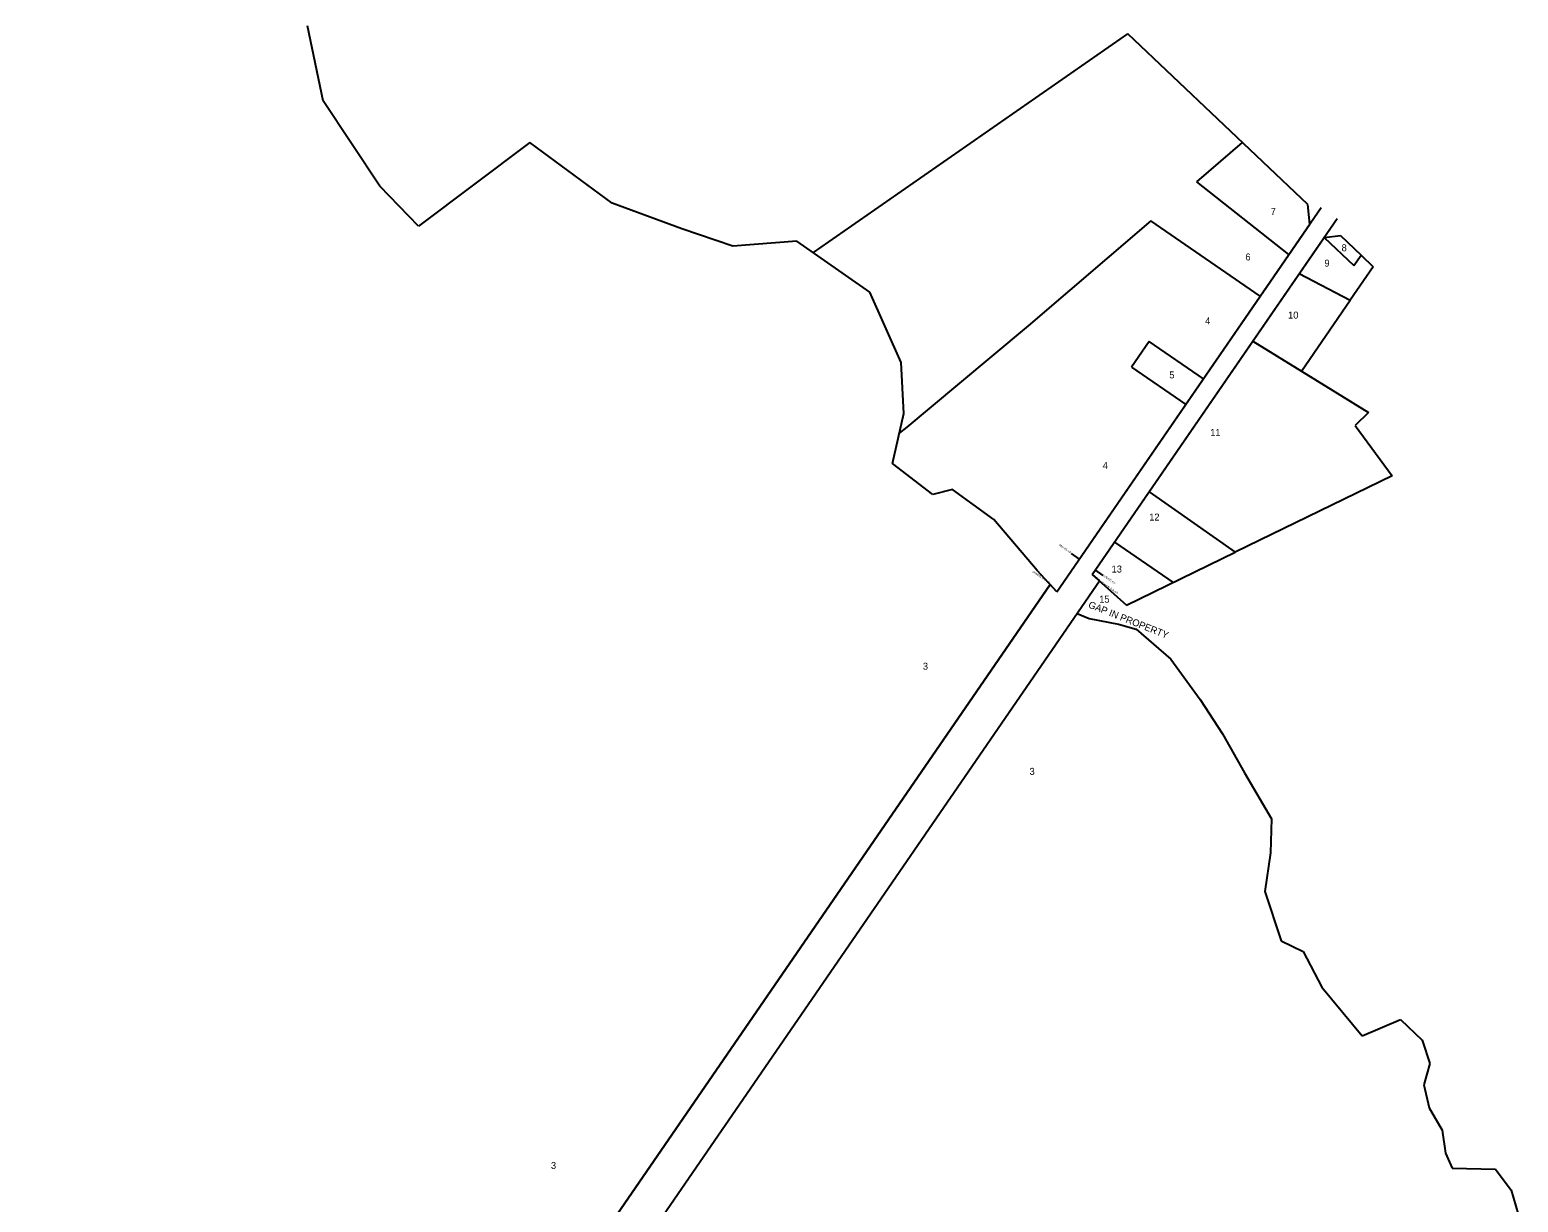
# Model space of a CAD drawing. Extents: x 2263676 to 2276182, y 713585 to 728175.
# Drawn here: x 2267281 to 2273100, y 720897 to 725479 of the extents above; entities that cross this region are included whole.
import ezdxf

# ---------------------------------------------------------------- set-up
doc = ezdxf.new("R2010")
doc.units = 0
for name, color, linetype in [('RD_EX_DV_Prop', 7, 'Continuous'), ('RD_EX_DV_TX_Prop', 7, 'Continuous'), ('RD_EX_RW', 7, 'Continuous'), ('RD_EX_RW_TX', 7, 'Continuous')]:
    doc.layers.add(name, color=color, linetype=linetype)

msp = doc.modelspace()

# ---------------------------------------------------------------- linework, layer by layer
at = {"layer": 'RD_EX_DV_Prop'}
for p, q in [((2268428.3, 725200.8), (2268367, 725494.5)), ((2270344.2, 724608.1), (2271573.6, 725463.6)), ((2272277.7, 724795.6), (2271573.6, 725463.6)), ((2268649.9, 724867.8), (2268428.3, 725200.8)), ((2269236.1, 725038.5), (2268801, 724712)), ((2269558.2, 724801.4), (2269236.1, 725038.5)), ((2271843, 724885), (2272022.3, 725037.9)), ((2272203.6, 724600.8), (2271843, 724885)), ((2268801, 724712), (2268649.9, 724867.8)), ((2269830.2, 724700.8), (2269558.2, 724801.4)), ((2272285.6, 724720), (2272277.7, 724795.6)), ((2271664.1, 724732.3), (2271183.4, 724322.5)), ((2271296.3, 723282.3), (2272285.6, 724720)), ((2272091.2, 724437.5), (2271664.1, 724732.3)), ((2270028.9, 724632.9), (2269830.2, 724700.8)), ((2270280.1, 724652.9), (2270028.9, 724632.9)), ((2270565.4, 724453.6), (2270280.1, 724652.9)), ((2271434.4, 723350.7), (2272340.7, 724667.8)), ((2272340.7, 724667.8), (2272405.3, 724674.5)), ((2272340.7, 724667.8), (2272456.8, 724557.6)), ((2272405.3, 724674.5), (2272485.1, 724598.8)), ((2272456.8, 724557.6), (2272485.1, 724598.8)), ((2272485.1, 724598.8), (2272533.3, 724553.1)), ((2272533.3, 724553.1), (2272443.2, 724422.1)), ((2272243.1, 724526), (2272443.2, 724422.1)), ((2270687.2, 724179.4), (2270565.4, 724453.6)), ((2272252.6, 724144.9), (2272443.2, 724422.1)), ((2271183.4, 724322.5), (2270907.7, 724091.1)), ((2271656.6, 724261), (2271587.4, 724160.5)), ((2271869.1, 724114.7), (2271656.6, 724261)), ((2272062, 724262.7), (2272252.6, 724144.9)), ((2270697.9, 723979.7), (2270687.2, 724179.4)), ((2271587.4, 724160.5), (2271799.9, 724014.2)), ((2272252.6, 724144.9), (2272514.5, 723982.9)), ((2270907.7, 724091.1), (2270709.2, 723926.1)), ((2270653.3, 723784.7), (2270697.9, 723979.7)), ((2272514.5, 723982.9), (2272462, 723932.3)), ((2270709.2, 723926.1), (2270680.1, 723902)), ((2272462, 723932.3), (2272606.8, 723736.5)), ((2270811.6, 723662.4), (2270653.3, 723784.7)), ((2272606.8, 723736.5), (2271993.7, 723437.7)), ((2270888, 723682.4), (2270811.6, 723662.4)), ((2271049.9, 723565), (2270888, 723682.4)), ((2271656.6, 723673.7), (2271993.7, 723437.7)), ((2271219.3, 723366.4), (2271049.9, 723565)), ((2271521.1, 723476.7), (2271751.3, 723319.6)), ((2271568.8, 723230.6), (2271993.7, 723437.7)), ((2271270.3, 723310.7), (2267281.1, 717513.7)), ((2267483.5, 717543.2), (2271462.6, 723325.5)), ((2271296.3, 723282.3), (2271219.3, 723366.4)), ((2271434.4, 723350.7), (2271568.8, 723230.6)), ((2271375.1, 723198.4), (2271422.7, 723178)), ((2271422.7, 723178), (2271537.6, 723155.9)), ((2271537.6, 723155.9), (2271605.9, 723136.5)), ((2271605.9, 723136.5), (2271741.2, 723019.4)), ((2271741.2, 723019.4), (2271856.2, 722861.9)), ((2271856.2, 722861.9), (2271944.2, 722727.1)), ((2271944.2, 722727.1), (2272030.3, 722574.7)), ((2272030.3, 722574.7), (2272134.7, 722394.8)), ((2272134.7, 722394.8), (2272130.8, 722262.9)), ((2272130.8, 722262.9), (2272109, 722111.4)), ((2272109, 722111.4), (2272173.6, 721918)), ((2272173.6, 721918), (2272259.1, 721876.5)), ((2272259.1, 721876.5), (2272331.9, 721737.4)), ((2272331.9, 721737.4), (2272489.4, 721547.2)), ((2272489.4, 721547.2), (2272639.3, 721611.2)), ((2272639.3, 721611.2), (2272723.7, 721530.1)), ((2272723.7, 721530.1), (2272754.1, 721439.1)), ((2272754.1, 721439.1), (2272730.3, 721355.4)), ((2272730.3, 721355.4), (2272751.5, 721265.9)), ((2272751.5, 721265.9), (2272802.2, 721178.5)), ((2272802.2, 721178.5), (2272814.9, 721089.4)), ((2272814.9, 721089.4), (2272842.1, 721030.4)), ((2272842.1, 721030.4), (2273011, 721026.8)), ((2273011, 721026.8), (2273072.5, 720944.2)), ((2273072.5, 720944.2), (2273099.7, 720850))]:
    msp.add_line(p, q, dxfattribs=at)
at = {"layer": 'RD_EX_RW'}
for p, q in [((2271296.3, 723282.3), (2272329.6, 724783.9)), ((2271434.4, 723350.7), (2272391.4, 724741.3)), ((2267281.1, 717513.7), (2271270.3, 723310.7)), ((2267483.5, 717543.2), (2271462.6, 723325.5)), ((2271296.3, 723282.3), (2271270.3, 723310.7)), ((2271434.4, 723350.7), (2271462.6, 723325.5))]:
    msp.add_line(p, q, dxfattribs=at)
at = {"layer": 'RD_EX_RW_TX'}
for p, q in [((2271384.5, 723410.5), (2271353.6, 723431.8)), ((2271477.2, 723346.7), (2271446.3, 723368))]:
    msp.add_line(p, q, dxfattribs=at)

# ---------------------------------------------------------------- texts
at = {"layer": 'RD_EX_DV_TX_Prop'}
for s, height, p in [('7', 27.2, (2272132.1, 724755.3)), ('6', 27.2, (2272033, 724577.6)), ('8', 27.2, (2272409.3, 724613.6)), ('9', 27.2, (2272342.1, 724553.4)), ('10', 27.16, (2272200, 724350.4)), ('4', 27.2, (2271875.9, 724328.3)), ('5', 27.2, (2271735.9, 724116.5)), ('11', 27.16, (2271895.5, 723891.7)), ('4', 27.2, (2271475, 723762.3)), ('12', 27.16, (2271657.2, 723561.2)), ('13', 27.16, (2271510.1, 723358)), ('15', 27.16, (2271461.6, 723240.1)), ('3', 27.2, (2270772.3, 722978.3)), ('3', 27.2, (2271189.4, 722567.4)), ('3', 27.2, (2269318.5, 721027.2))]:
    msp.add_text(s, height=height, dxfattribs=at).set_placement(p)
msp.add_text('GAP IN PROPERTY', height=27.158, rotation=338.27351, dxfattribs=at).set_placement((2271416.7, 723222))
at = {"layer": 'RD_EX_RW_TX'}
for s, p in [('436+65 rcb', (2271303.4, 723463.7)), ('property line rcb', (2271200.5, 723359.6)), ('property line rcb', (2271467.8, 723318.1)), ('436+65 rcb', (2271476.4, 723343.1))]:
    msp.add_text(s, height=8, rotation=325.46633, dxfattribs=at).set_placement(p)

doc.saveas('drawing.dxf')
